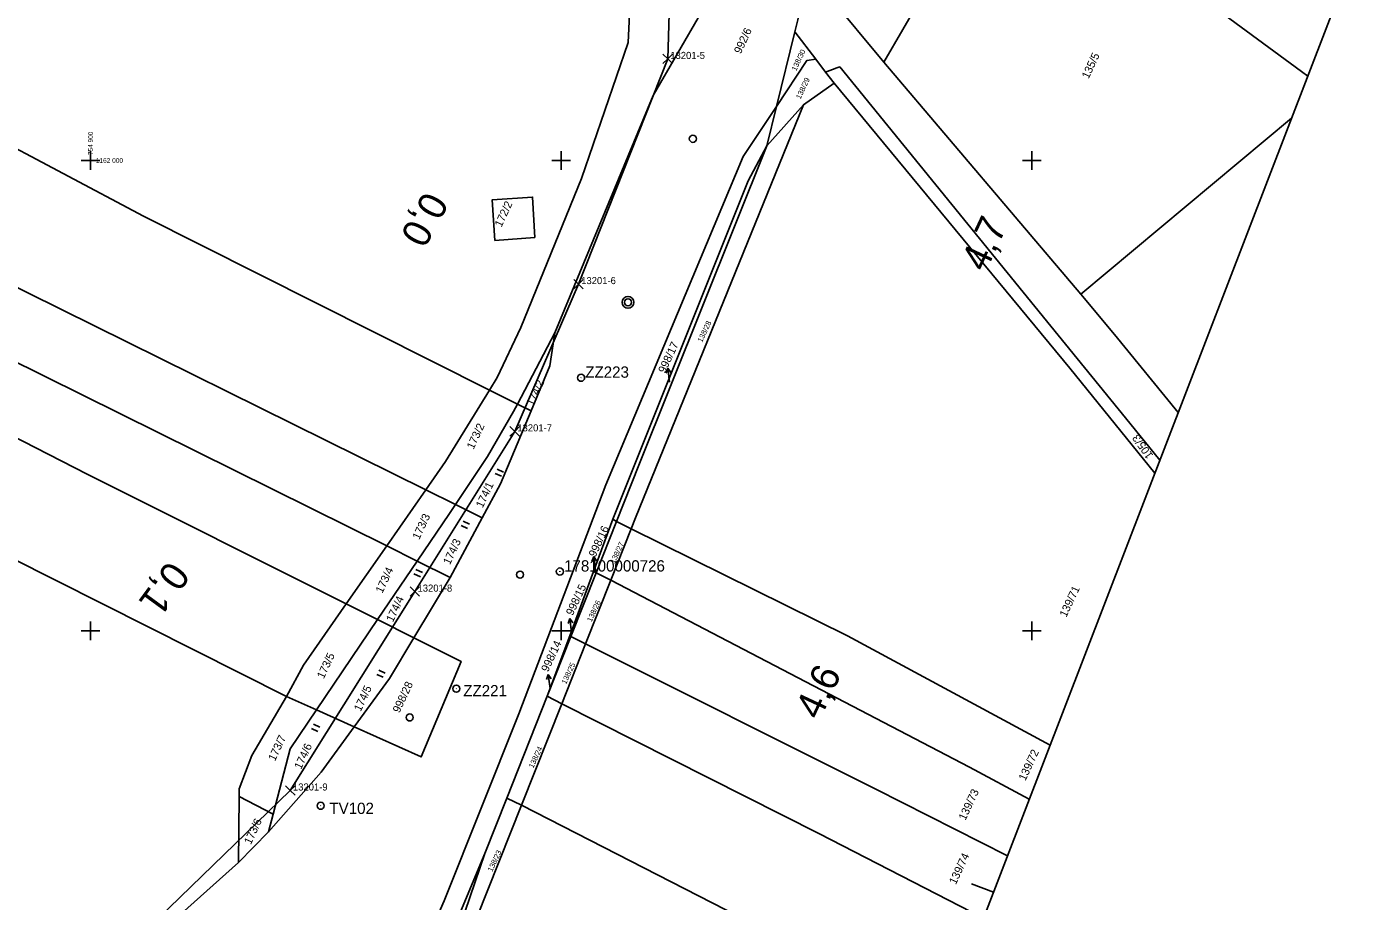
# Model space of a CAD drawing. Extents: x -755061 to -754557, y -1162352 to -1161657.
# Drawn here: x -754913.6 to -754632.7, y -1162157.5 to -1161971.5 of the extents above; entities that cross this region are included whole.
import ezdxf

# ---------------------------------------------------------------- set-up
doc = ezdxf.new("R2010")
doc.units = 0
for name, color, linetype in [('Body ŽBP', 7, 'Continuous'), ('Formát', 7, 'Continuous'), ('Katastrální hranice', 7, 'Continuous'), ('SO_01_32_01', 7, 'Continuous'), ('Staniceni a namezniky', 7, 'Continuous'), ('Síť', 7, 'Continuous'), ('VB_01_32_01', 7, 'Continuous'), ('Vrstva 55', 7, 'Continuous'), ('Vrstva 57', 7, 'Continuous'), ('Vrstva 58', 7, 'Continuous')]:
    doc.layers.add(name, color=color, linetype=linetype)

msp = doc.modelspace()

# ---------------------------------------------------------------- linework, layer by layer
at = {"layer": 'Body ŽBP'}
for p, q in [((-754795.75, -1162046.13), (-754795.79, -1162046.22)), ((-754795.77, -1162046.18), (-754795.77, -1162046.18)), ((-754800.25, -1162087.33), (-754800.29, -1162087.43)), ((-754800.27, -1162087.38), (-754800.27, -1162087.38)), ((-754822.9, -1162111.96), (-754822.9, -1162111.96)), ((-754822.26, -1162112.23), (-754822.3, -1162112.32)), ((-754822.28, -1162112.28), (-754822.28, -1162112.28)), ((-754851.08, -1162137.12), (-754851.12, -1162137.22)), ((-754851.1, -1162137.17), (-754851.1, -1162137.17))]:
    msp.add_line(p, q, dxfattribs=at)
for centre in [(-754795.77, -1162046.18), (-754800.27, -1162087.38), (-754822.28, -1162112.28), (-754851.1, -1162137.17)]:
    msp.add_circle(centre, 0.756, dxfattribs=at)
at = {"layer": 'Formát'}
msp.add_line((-754708.14, -1162155.53), (-754712.81, -1162153.74), dxfattribs=at)
msp.add_lwpolyline([(-754909.9, -1161852.87), (-754632.71, -1161959.54), (-754783.57, -1162351.52), (-755060.75, -1162244.84)], close=True, dxfattribs=at)
at = {"layer": 'Katastrální hranice'}
for p, q in [((-754754.27, -1161988.55), (-754750.32, -1161972.64)), ((-754754.27, -1161988.55), (-754756.33, -1161996.85)), ((-754756.33, -1161996.85), (-754783.47, -1162064.75)), ((-754783.47, -1162064.75), (-754788.22, -1162076.73)), ((-754788.22, -1162076.73), (-754792.54, -1162087.63)), ((-754792.54, -1162087.63), (-754797.91, -1162101.16)), ((-754797.91, -1162101.16), (-754802.96, -1162113.9)), ((-754802.96, -1162113.9), (-754811.54, -1162135.54)), ((-754811.54, -1162135.54), (-754816.22, -1162147.35))]:
    msp.add_line(p, q, dxfattribs=at)
for points in [[(-754750.32, -1161972.64), (-754749.74, -1161970.12), (-754747.74, -1161961.29), (-754747.41, -1161959.83)], [(-754816.22, -1162147.35), (-754851.45, -1162231.96), (-754884.82, -1162312.55)]]:
    msp.add_lwpolyline(points, dxfattribs=at)
at = {"layer": 'SO_01_32_01'}
msp.add_lwpolyline([(-754758.34, -1161933.06), (-754762.34, -1161937.68), (-754763.29, -1161936.85), (-754776.47, -1161949.62), (-754777.37, -1161978.41), (-754796.3, -1162026.28), (-754809.87, -1162057.58), (-754831.07, -1162091.65), (-754857.54, -1162133.93), (-754885.68, -1162161.18), (-754896.77, -1162171.93), (-754916.86, -1162186.18), (-754942.05, -1162200.54), (-754965.03, -1162211.64), (-754990.89, -1162220.78), (-755014.11, -1162227.27), (-755008.76, -1162253.14), (-755005.05, -1162256.17)], dxfattribs=at)
at = {"layer": 'Staniceni a namezniky'}
for centre, radius in [((-754772.02, -1161995.39), 0.75), ((-754785.8, -1162030.15), 1.25), ((-754785.8, -1162030.15), 0.752), ((-754808.73, -1162088.04), 0.75), ((-754832.17, -1162118.4), 0.75)]:
    msp.add_circle(centre, radius, dxfattribs=at)
at = {"layer": 'Síť'}
for points in [[(-754900, -1161998), (-754900, -1162000), (-754900, -1162002)], [(-754800, -1161998), (-754800, -1162000), (-754800, -1162002)], [(-754700, -1161998), (-754700, -1162000), (-754700, -1162002)], [(-754898, -1162000), (-754900, -1162000), (-754902, -1162000)], [(-754798, -1162000), (-754800, -1162000), (-754802, -1162000)], [(-754698, -1162000), (-754700, -1162000), (-754702, -1162000)], [(-754898, -1162100), (-754900, -1162100), (-754902, -1162100)], [(-754900, -1162098), (-754900, -1162100), (-754900, -1162102)], [(-754798, -1162100), (-754800, -1162100), (-754802, -1162100)], [(-754800, -1162098), (-754800, -1162100), (-754800, -1162102)], [(-754698, -1162100), (-754700, -1162100), (-754702, -1162100)], [(-754700, -1162098), (-754700, -1162100), (-754700, -1162102)]]:
    msp.add_lwpolyline(points, dxfattribs=at)
at = {"layer": 'VB_01_32_01'}
for p, q in [((-754777.37, -1161978.41), (-754778.37, -1161977.41)), ((-754777.37, -1161978.41), (-754778.37, -1161979.41)), ((-754777.37, -1161978.41), (-754776.37, -1161977.41)), ((-754777.37, -1161978.41), (-754776.37, -1161979.41)), ((-754796.3, -1162026.28), (-754797.3, -1162025.28)), ((-754796.3, -1162026.28), (-754797.3, -1162027.28)), ((-754796.3, -1162026.28), (-754795.3, -1162025.28)), ((-754796.3, -1162026.28), (-754795.3, -1162027.28)), ((-754809.87, -1162057.58), (-754810.87, -1162056.58)), ((-754809.87, -1162057.58), (-754810.87, -1162058.58)), ((-754809.87, -1162057.58), (-754808.87, -1162056.58)), ((-754809.87, -1162057.58), (-754808.87, -1162058.58)), ((-754831.07, -1162091.65), (-754832.07, -1162090.65)), ((-754831.07, -1162091.65), (-754832.07, -1162092.65)), ((-754831.07, -1162091.65), (-754830.07, -1162090.65)), ((-754831.07, -1162091.65), (-754830.07, -1162092.65)), ((-754857.54, -1162133.93), (-754858.54, -1162132.93)), ((-754857.54, -1162133.93), (-754858.54, -1162134.93)), ((-754857.54, -1162133.93), (-754856.54, -1162132.93)), ((-754857.54, -1162133.93), (-754856.54, -1162134.93))]:
    msp.add_line(p, q, dxfattribs=at)
at = {"layer": 'Vrstva 55'}
for p, q in [((-754717.5, -1161955.11), (-754731.42, -1161979.09)), ((-754731.42, -1161979.09), (-754747.41, -1161959.83)), ((-754754.27, -1161988.55), (-754750.32, -1161972.64)), ((-754754.27, -1161988.55), (-754750.32, -1161972.64)), ((-754750.32, -1161972.64), (-754745.89, -1161978.47)), ((-754745.89, -1161978.47), (-754743.83, -1161981.19)), ((-754689.56, -1162028.42), (-754731.42, -1161979.09)), ((-754743.83, -1161981.19), (-754742.02, -1161983.57)), ((-754742.02, -1161983.57), (-754748.48, -1161988.2)), ((-754748.48, -1161988.2), (-754784.18, -1162075.95)), ((-754748.48, -1161988.2), (-754756.33, -1161996.85)), ((-754754.27, -1161988.55), (-754756.33, -1161996.85)), ((-754754.27, -1161988.55), (-754756.33, -1161996.85)), ((-754689.56, -1162028.42), (-754644.83, -1161991.02)), ((-754756.33, -1161996.85), (-754783.47, -1162064.75)), ((-754756.33, -1161996.85), (-754783.47, -1162064.75)), ((-754682.41, -1162036.96), (-754689.56, -1162028.42)), ((-754809.29, -1162051.78), (-754801.36, -1162036.63)), ((-754668.89, -1162053.54), (-754682.41, -1162036.96)), ((-754815.21, -1162048.8), (-754809.29, -1162051.78)), ((-754806.4, -1162053.23), (-754809.29, -1162051.78)), ((-754783.47, -1162064.75), (-754788.22, -1162076.73)), ((-754783.47, -1162064.75), (-754788.22, -1162076.73)), ((-754828.75, -1162070.02), (-754837.06, -1162081.94)), ((-754828.75, -1162070.02), (-754822.47, -1162073.13)), ((-754822.47, -1162073.13), (-754816.76, -1162075.96)), ((-754816.76, -1162075.96), (-754823.58, -1162088.63)), ((-754793.13, -1162087.4), (-754789, -1162076.26)), ((-754788.22, -1162076.73), (-754792.54, -1162087.63)), ((-754788.22, -1162076.73), (-754792.54, -1162087.63)), ((-754788.22, -1162076.73), (-754789, -1162076.26)), ((-754785.12, -1162078.33), (-754788.22, -1162076.73)), ((-754784.18, -1162075.95), (-754785.12, -1162078.33)), ((-754785.12, -1162078.33), (-754789.45, -1162089.23)), ((-754837.06, -1162081.94), (-754845.66, -1162094.27)), ((-754837.06, -1162081.94), (-754830.58, -1162085.16)), ((-754839, -1162097.61), (-754830.58, -1162085.16)), ((-754830.58, -1162085.16), (-754823.58, -1162088.63)), ((-754823.58, -1162088.63), (-754831.28, -1162101.48)), ((-754798.15, -1162101.07), (-754793.13, -1162087.4)), ((-754792.54, -1162087.63), (-754797.91, -1162101.16)), ((-754792.54, -1162087.63), (-754797.91, -1162101.16)), ((-754789.45, -1162089.23), (-754794.8, -1162102.72)), ((-754792.54, -1162087.63), (-754793.13, -1162087.4)), ((-754789.45, -1162089.23), (-754792.54, -1162087.63)), ((-754845.66, -1162094.27), (-754839, -1162097.61)), ((-754851.98, -1162116.8), (-754839, -1162097.61)), ((-754839, -1162097.61), (-754831.28, -1162101.48)), ((-754802.96, -1162113.9), (-754798.15, -1162101.07)), ((-754797.91, -1162101.16), (-754802.96, -1162113.9)), ((-754797.91, -1162101.16), (-754802.96, -1162113.9)), ((-754794.8, -1162102.72), (-754799.86, -1162115.47)), ((-754797.91, -1162101.16), (-754798.15, -1162101.07)), ((-754794.8, -1162102.72), (-754797.91, -1162101.16)), ((-754858.37, -1162113.93), (-754851.98, -1162116.8)), ((-754802.96, -1162113.9), (-754811.54, -1162135.54)), ((-754802.96, -1162113.9), (-754811.54, -1162135.54)), ((-754799.86, -1162115.47), (-754802.96, -1162113.9)), ((-754851.98, -1162116.8), (-754843.96, -1162120.41)), ((-754799.86, -1162115.47), (-754808.43, -1162137.05)), ((-754868.56, -1162149.23), (-754868.42, -1162135.23)), ((-754861.18, -1162138.93), (-754868.42, -1162135.23)), ((-754808.43, -1162137.05), (-754817.91, -1162160.94)), ((-754811.54, -1162135.54), (-754816.22, -1162147.35)), ((-754811.54, -1162135.54), (-754816.22, -1162147.35)), ((-754808.43, -1162137.05), (-754811.54, -1162135.54)), ((-754862.16, -1162142.69), (-754861.18, -1162138.93)), ((-754868.56, -1162149.23), (-754862.16, -1162142.69)), ((-754820.38, -1162159.55), (-754816.22, -1162147.35))]:
    msp.add_line(p, q, dxfattribs=at)
for points in [[(-754790.69, -1161920.17), (-754784.8, -1161953.94), (-754785.77, -1161974.89), (-754795.69, -1162003.82), (-754808.6, -1162035.49), (-754813.58, -1162046.15), (-754815.21, -1162048.8)], [(-754641.37, -1161982.04), (-754642.71, -1161981.11), (-754670.75, -1161960.4), (-754682.08, -1161945.77), (-754685.37, -1161939.28)], [(-754764.95, -1161959.34), (-754780.44, -1161986.21), (-754801.36, -1162036.63)], [(-754750.32, -1161972.64), (-754749.74, -1161970.12), (-754747.74, -1161961.29), (-754747.41, -1161959.83)], [(-754750.32, -1161972.64), (-754749.74, -1161970.12), (-754747.74, -1161961.29), (-754747.41, -1161959.83)], [(-754957.1, -1161975.52), (-754888.73, -1162011.84), (-754815.21, -1162048.8)], [(-754745.89, -1161978.47), (-754747.84, -1161978.77), (-754754.27, -1161988.55)], [(-754672.81, -1162063.72), (-754680.12, -1162054.72), (-754695.96, -1162035.25), (-754716.99, -1162009.36), (-754740.8, -1161980.09), (-754741.4, -1161980.31), (-754743.83, -1161981.19)], [(-754742.02, -1161983.57), (-754691.91, -1162044.14), (-754673.85, -1162066.44)], [(-754888.68, -1162311.07), (-754870.17, -1162267.96), (-754836.4, -1162183.6), (-754824.89, -1162157.4), (-754808.97, -1162117.64), (-754790.52, -1162068.93), (-754761.32, -1161999.17), (-754754.27, -1161988.55)], [(-754789, -1162076.26), (-754760.29, -1162004.33), (-754756.33, -1161996.85)], [(-754966.42, -1161999.75), (-754920.4, -1162024.65), (-754828.75, -1162070.02)], [(-754805.56, -1162016.36), (-754806.06, -1162007.78), (-754814.69, -1162008.38), (-754814.09, -1162016.99), (-754805.56, -1162016.36)], [(-754971.75, -1162013.61), (-754934.11, -1162033.82), (-754837.06, -1162081.94)], [(-754977.09, -1162027.47), (-754900.68, -1162066.68), (-754845.66, -1162094.27)], [(-754801.36, -1162036.63), (-754802.42, -1162043.68), (-754806.4, -1162053.23)], [(-754858.37, -1162113.93), (-754985.69, -1162049.81)], [(-754815.21, -1162048.8), (-754824.54, -1162063.98), (-754828.75, -1162070.02)], [(-754822.47, -1162073.13), (-754815.64, -1162062.89), (-754810.12, -1162053.37), (-754809.29, -1162051.78)], [(-754806.4, -1162053.23), (-754812.88, -1162068.75), (-754816.76, -1162075.96)], [(-754830.58, -1162085.16), (-754823.72, -1162075.01), (-754822.47, -1162073.13)], [(-754785.12, -1162078.33), (-754739.17, -1162101.03), (-754696.12, -1162124.29)], [(-754789.45, -1162089.23), (-754713.23, -1162128.96), (-754700.55, -1162135.8)], [(-754845.66, -1162094.27), (-754854.71, -1162107.25), (-754858.37, -1162113.93)], [(-754843.96, -1162120.41), (-754836.46, -1162110.13), (-754831.28, -1162101.48)], [(-754831.28, -1162101.48), (-754821.22, -1162106.53), (-754829.74, -1162126.8), (-754843.96, -1162120.41)], [(-754794.8, -1162102.72), (-754733.16, -1162133.64), (-754705.18, -1162147.85)], [(-754868.42, -1162135.23), (-754868.4, -1162133.56), (-754865.75, -1162126.5), (-754858.37, -1162113.93)], [(-754861.18, -1162138.93), (-754857.56, -1162125.05), (-754851.98, -1162116.8)], [(-754799.86, -1162115.47), (-754745.23, -1162143.07), (-754710.27, -1162161.07)], [(-754862.16, -1162142.69), (-754850.97, -1162130.01), (-754843.96, -1162120.41)], [(-754808.43, -1162137.05), (-754718.71, -1162183.01)], [(-754816.22, -1162147.35), (-754851.45, -1162231.96), (-754884.82, -1162312.55)], [(-754816.22, -1162147.35), (-754851.45, -1162231.96), (-754884.82, -1162312.55)], [(-754900.06, -1162176.77), (-754896.07, -1162173.88), (-754868.56, -1162149.23)]]:
    msp.add_lwpolyline(points, dxfattribs=at)
at = {"layer": 'Vrstva 57'}
for p, q in [((-754777.34, -1162044.16), (-754777.71, -1162045.22)), ((-754776.95, -1162047.14), (-754777.34, -1162044.16)), ((-754777.34, -1162044.16), (-754776.71, -1162045.09)), ((-754793.08, -1162084.2), (-754793.45, -1162085.25)), ((-754792.69, -1162087.17), (-754793.08, -1162084.2)), ((-754793.08, -1162084.2), (-754792.46, -1162085.12)), ((-754798.16, -1162097.38), (-754798.52, -1162098.44)), ((-754797.77, -1162100.36), (-754798.16, -1162097.38)), ((-754798.16, -1162097.38), (-754797.53, -1162098.31)), ((-754802.74, -1162109.29), (-754803.11, -1162110.34)), ((-754802.35, -1162112.26), (-754802.74, -1162109.29)), ((-754802.74, -1162109.29), (-754802.11, -1162110.22))]:
    msp.add_line(p, q, dxfattribs=at)
at = {"layer": 'Vrstva 58'}
for p, q in [((-754812.68, -1162067.14), (-754814.04, -1162066.51)), ((-754812.25, -1162066.23), (-754813.61, -1162065.6)), ((-754819.87, -1162078.2), (-754821.23, -1162077.56)), ((-754819.44, -1162077.29), (-754820.8, -1162076.65)), ((-754829.91, -1162088.5), (-754831.27, -1162087.87)), ((-754829.49, -1162087.6), (-754830.85, -1162086.96)), ((-754837.38, -1162108.96), (-754838.74, -1162108.33)), ((-754837.8, -1162109.87), (-754839.16, -1162109.24)), ((-754851.25, -1162120.45), (-754852.61, -1162119.82)), ((-754851.67, -1162121.36), (-754853.03, -1162120.72))]:
    msp.add_line(p, q, dxfattribs=at)

# ---------------------------------------------------------------- texts
at = {"layer": 'Body ŽBP'}
for s, p in [(' ZZ223', (-754795.77, -1162046.18)), (' 178100000726', (-754800.27, -1162087.38)), (' ZZ221', (-754821.69, -1162113.91)), (' TV102', (-754850.13, -1162138.92))]:
    msp.add_text(s, height=2.4, dxfattribs=at).set_placement(p)
at = {"layer": 'Staniceni a namezniky'}
for s, rotation, p in [('0,0', 241.5098, (-754828.98, -1162006.23)), ('4,7', 64.9752, (-754709.84, -1162023.92)), ('0,1', 233.7782, (-754883.38, -1162084.78)), ('4,6', 64.9752, (-754745.07, -1162119.17))]:
    msp.add_text(s, height=6, rotation=rotation, dxfattribs=at).set_placement(p)
at = {"layer": 'Síť'}
msp.add_text('   754 900', height=1, rotation=90, dxfattribs=at).set_placement((-754899.5, -1162000))
msp.add_text('   1162 000', height=1, dxfattribs=at).set_placement((-754900, -1162000.5))
at = {"layer": 'VB_01_32_01'}
for s, p in [(' 13201-5', (-754777.37, -1161978.41)), (' 13201-6', (-754796.3, -1162026.28)), (' 13201-7', (-754809.87, -1162057.58)), (' 13201-8', (-754831.07, -1162091.65)), (' 13201-9', (-754857.54, -1162133.93))]:
    msp.add_text(s, height=1.5, dxfattribs=at).set_placement(p)
at = {"layer": 'Vrstva 57'}
for s, height, rotation, p in [('992/6', 1.7, 65, (-754761.84, -1161977.46)), ('138/30', 1.139, 65, (-754750.08, -1161981.08)), ('135/5', 1.7, 65, (-754687.95, -1161982.76)), ('138/29', 1.139, 65, (-754749.15, -1161987.06)), ('172/2', 1.7, 65, (-754812.69, -1162014.3)), ('138/28', 1.139, 65, (-754770.07, -1162038.77)), ('998/17', 1.7, 65, (-754777.94, -1162045.36)), ('174/2', 1.7, 65, (-754805.96, -1162052.31)), ('173/2', 1.7, 65, (-754818.62, -1162061.53)), ('105/3', 1.7, 124.8536, (-754674.15, -1162062.7)), ('174/1', 1.7, 65, (-754816.69, -1162074)), ('173/3', 1.7, 65, (-754830.16, -1162080.73)), ('998/16', 1.7, 65, (-754792.72, -1162084.46)), ('174/3', 1.7, 65, (-754823.64, -1162086.08)), ('138/27', 1.139, 65, (-754788.63, -1162085.8)), ('173/4', 1.7, 65, (-754837.99, -1162092.13)), ('998/15', 1.7, 65, (-754797.54, -1162096.87)), ('139/71', 1.7, 65, (-754692.69, -1162097.23)), ('174/4', 1.7, 65, (-754835.75, -1162098.26)), ('138/26', 1.139, 65, (-754793.55, -1162098.19)), ('998/14', 1.7, 65, (-754802.81, -1162108.87)), ('173/5', 1.7, 65, (-754850.44, -1162110.31)), ('138/25', 1.139, 65, (-754798.97, -1162111.43)), ('174/5', 1.7, 65, (-754842.59, -1162117.26)), ('998/28', 1.7, 65, (-754834.36, -1162117.56)), ('173/7', 1.7, 65, (-754860.8, -1162127.81)), ('174/6', 1.7, 65, (-754855.26, -1162129.56)), ('138/24', 1.139, 65, (-754805.94, -1162129.27)), ('139/72', 1.7, 65, (-754701.38, -1162132.01)), ('139/73', 1.7, 65, (-754714.12, -1162140.41)), ('173/6', 1.7, 65, (-754865.93, -1162145.53)), ('138/23', 1.139, 65, (-754814.66, -1162151.31)), ('139/74', 1.7, 65, (-754716.15, -1162154.04))]:
    msp.add_text(s, height=height, rotation=rotation, dxfattribs=at).set_placement(p)

doc.saveas('drawing.dxf')
